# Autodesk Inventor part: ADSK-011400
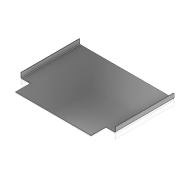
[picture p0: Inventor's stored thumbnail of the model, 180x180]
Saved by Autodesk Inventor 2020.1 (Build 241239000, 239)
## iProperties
Created: 2000-01
Part Number: ADSK-011400
Material: 1.0312 DC05
Document SubType Name: Tôlerie
Designer: glanglot
Density: 1 g/cm^3
Sheet Metal Rule: Stahlblech 1.0312 - DC05 -   1.5mm
Appearance: Chrom - poliert
Mass: 77.6181 g
Surface Area: 1049.15 cm^2
Volume: 77.6181 cm^3
Flat Pattern Width: 19.7 cm
Flat Pattern Length: 27.7586 cm
Flat Pattern Area: 546.844 cm^2
Sheet Metal Width: 197,000 mm
Sheet Metal Length: 277,586 mm
Sheet Metal Area: 54684,411 mm^2
Control State: 0
Checked Out: False
Master: False
Shininess: 57.0
Length Units: 11269
Angle Units: 11279
Time Units: 11290
Mass Units: 11283
Length Display Precision: 3
Angle Display Precision: 2
Compacted: True
CUTLENGTH: 7.75 10.91 (85 SI)
MATERIAL DESC: SHEET,S/S, 16 GA
MATERIAL_NUMBER: A084639
G_L: 277,6x197 mm
Thickness: 1,500 mm
Dimensions: 254,8x14x197 mm
Mass: 0,078 kg
Semi finished: Stahlblech 1.0312 - DC05 -   1.5mm
Density: 8.03
Volumn: 81.81487011799034
Area: 1045.790575201847
PropertySet Name: Model Information
Author: glanglot
Revision Number: -
Title: ADSK-011400
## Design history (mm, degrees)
sketch "Sketch1"
  geometry: L1 (127.4, 14)-(127.4, 0); L2 (127.4, 0)-(-127.4, 0); L3 (-127.4, 0)-(-127.4, 14); L4 (0, 0)-(0, 14); 1 further point
  constraints: 8 end point, 2 horizontal alignment, 2 perpendicular, 1 coincident, 1 horizontal, 1 midpoint
  dimensions: "d8" = 254.8 distance between parallel lines of L1 L3; "d13" = 14 distance of L1.start L1.end
sketch "Sketch2"
  geometry: L1 (-25.5, -58.5)-(-25.5, -98.5); L2 (34.5, -98.5)-(-25.5, -98.5); L3 (-25.5, -58.5)-(34.5, -58.5); L4 (251.4, 98.5)-(251.4, -98.5) reference; L5 (-2.6, 98.5)-(-251.4, 98.5) reference; L6 (-251.4, -98.5)-(-2.6, -98.5) reference; L7 (-127, 98.5)-(-127, -98.5); L8 (34.5, -58.5)-(34.5, -98.5); L9 (-288.5, -58.5)-(-288.5, -98.5); L10 (-228.5, -98.5)-(-288.5, -98.5); L11 (-288.5, -58.5)-(-228.5, -58.5); L12 (-228.5, -58.5)-(-228.5, -98.5)
  constraints: 18 end point, 2 collinear, 2 midpoint, 2 parallel, 2 perpendicular, 2 vertical
  dimensions: "d25" = 101.5 distance between parallel lines of L7 L1; "d26" = 40 distance of L1.start L1.end; "d27" = 60 distance of L1.start L3.end; "d28" = 40 distance of L9.start L9.end; "d29" = 60 distance of L9.start L11.end; "d30" = 101.5 distance between parallel lines of L7 L12 (= d25)
feature "Ausklinkung1" dims "d31" = 1.5 (= Thickness), "d32" = 0
feature "Grobblech1" dims "d14" = 1.5 (= Thickness), "d15" = 1.5 (= BendReliefWidth), "d16" = 0.75 (= BendReliefDepth), "d17" = 3 (= MinimumRemnant), "d18" = 1.5 (= TransitionRadius), "d19" = 197, "d20" = 1.5 (= BendRadius), "d21" = 1.588, "d22" = 6 (= CornerReliefSize), "d23" = 1.5 (= TailleJeu), "d24" = 1.5 (= TailleRayonJacobi), "SeamGap" = 0.00508
node "Volumenkörper2"
  node "Konturlasche1"
feature "Biegung1" dims "d14" = 1.5 (= Thickness), "d15" = 1.5 (= BendReliefWidth), "d16" = 0.75 (= BendReliefDepth), "d17" = 3 (= MinimumRemnant), "d18" = 1.5 (= TransitionRadius), "d20" = 1.5 (= BendRadius), "d21" = 1.588, "SeamGap" = 0.00508
feature "Ecke1" dims "d21" = 1.588, "d22" = 6 (= CornerReliefSize), "d23" = 1.5 (= TailleJeu), "d24" = 1.5 (= TailleRayonJacobi)
node "Solide1"
node "Corps solides"
node "Corps surfaciques"
feature "Definition1"
other parameters: "d0" = 1.5875, "Thickness" = 1.5 (derived), "BendRadius" = 1.5 (= Thickness), "BendReliefWidth" = 1.5 (= Thickness), "BendReliefDepth" = 0.75 (= 0.5 x Thickness), "CornerReliefSize" = 6 (= 4 x Thickness), "MinimumRemnant" = 3 (= 2 x Thickness), "TransitionRadius" = 1.5 (= BendRadius), "TailleRayonJacobi" = 1.5 (= BendRadius), "TailleJeu" = 1.5 (= Thickness), "BendRadius" = 1.5, "BendReliefDepth" = 0.75, "BendReliefWidth" = 1.5, "CornerReliefSize" = 6, "MinimumRemnant" = 3, "TailleJeu" = 1.5, "TailleRayonJacobi" = 1.5, "Thickness" = 1.5, "TransitionRadius" = 1.5
